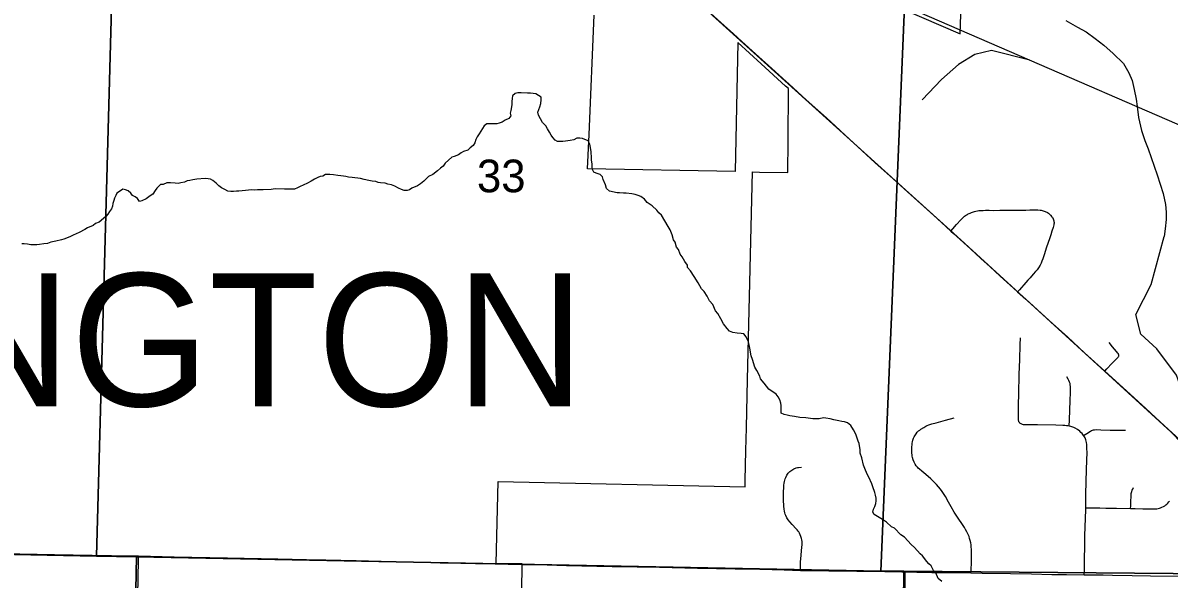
# Model space of a CAD drawing. Extents: x 0 to 34, y 0 to 22.
# Drawn here: x 25.012 to 25.746, y 18.367 to 18.723 of the extents above; entities that cross this region are included whole.
import ezdxf

# ---------------------------------------------------------------- set-up
doc = ezdxf.new("R2010")
doc.units = 0
for name, color, linetype in [('GM_X_City_Street', 7, 'Continuous'), ('GM_X_Corporation', 7, 'Continuous'), ('GM_X_County_Road', 7, 'Continuous'), ('GM_X_Major_River', 7, 'Continuous'), ('GM_X_Major_River_Text', 7, 'Continuous'), ('GM_X_Minor_River', 7, 'Continuous'), ('GM_X_Rail_Line', 7, 'Continuous'), ('GM_X_Section', 7, 'Continuous'), ('GM_X_Section_Text', 7, 'Continuous'), ('GM_X_State_Route', 7, 'Continuous'), ('GM_X_Township_Road', 7, 'Continuous'), ('GM_X_Township_Text', 7, 'Continuous'), ('GM_X_US_Route', 7, 'Continuous')]:
    doc.layers.add(name, color=color, linetype=linetype)

msp = doc.modelspace()

# ---------------------------------------------------------------- linework, layer by layer
at = {"layer": 'GM_X_City_Street'}
for points in [[(25.60654, 18.58985), (25.60774, 18.59127), (25.61008, 18.59407), (25.61296, 18.59711), (25.61376, 18.59796), (25.61444, 18.59863), (25.61534, 18.59937), (25.61649, 18.60019), (25.61713, 18.60055), (25.61771, 18.60086), (25.61892, 18.60142), (25.61964, 18.60174), (25.6204, 18.60204), (25.62097, 18.60223), (25.62159, 18.60241), (25.62258, 18.60264), (25.62356, 18.60284), (25.62434, 18.60297), (25.6257, 18.60309), (25.6273, 18.60317), (25.62866, 18.60319), (25.63106, 18.60318), (25.63353, 18.60316), (25.63795, 18.60319), (25.64313, 18.60328), (25.64983, 18.60334), (25.65463, 18.60338), (25.65722, 18.60342), (25.66006, 18.60344), (25.66228, 18.60342), (25.6638, 18.60329), (25.66448, 18.6032), (25.66508, 18.60309), (25.66577, 18.60292), (25.66639, 18.60272), (25.6669, 18.60252), (25.66746, 18.60229), (25.66801, 18.60201), (25.66853, 18.60172), (25.66906, 18.60135), (25.66955, 18.60098), (25.66998, 18.60057), (25.67043, 18.6001), (25.67124, 18.5991), (25.67153, 18.59868), (25.67177, 18.59828), (25.67208, 18.59766), (25.67235, 18.59701), (25.67251, 18.59642), (25.6726, 18.59591), (25.67264, 18.59536), (25.67266, 18.59488), (25.6726, 18.59437), (25.67247, 18.5938), (25.67227, 18.593), (25.672, 18.59213), (25.67128, 18.5899), (25.6705, 18.58747), (25.66964, 18.5848), (25.66887, 18.58248), (25.66766, 18.57897), (25.66651, 18.57535), (25.66545, 18.57206), (25.66491, 18.57058), (25.66433, 18.56922), (25.66368, 18.56803), (25.66265, 18.56635), (25.66175, 18.56507), (25.66084, 18.56392), (25.65928, 18.56215), (25.65735, 18.55998), (25.65591, 18.55849), (25.65447, 18.55697), (25.65044, 18.55229), (25.64924, 18.55089)], [(25.69204, 18.36949), (25.69207, 18.37266), (25.69215, 18.37961), (25.69228, 18.38766), (25.69236, 18.39038), (25.69248, 18.39453), (25.69294, 18.41109), (25.69296, 18.41238), (25.69311, 18.42103), (25.69354, 18.43688), (25.69378, 18.44836), (25.69376, 18.45006), (25.69366, 18.45168), (25.69359, 18.45297), (25.69342, 18.45416), (25.69327, 18.45503), (25.69302, 18.45592), (25.6928, 18.45664), (25.6925, 18.45731), (25.69211, 18.45799), (25.69162, 18.45872), (25.69061, 18.45996), (25.68981, 18.46078), (25.68909, 18.46144), (25.68765, 18.46255), (25.68611, 18.46349), (25.68542, 18.46383), (25.68475, 18.46412), (25.68332, 18.46458), (25.68227, 18.4648), (25.68155, 18.46493), (25.68061, 18.46506), (25.67946, 18.46518), (25.67818, 18.46525), (25.67386, 18.46538), (25.66207, 18.4656), (25.65491, 18.46557), (25.65391, 18.4656), (25.65342, 18.46564), (25.65297, 18.4657), (25.65249, 18.46581), (25.65196, 18.46599), (25.65151, 18.46622), (25.65109, 18.46647), (25.65079, 18.46673), (25.65055, 18.467), (25.65034, 18.46728), (25.65018, 18.46762), (25.65005, 18.46794), (25.64995, 18.46829), (25.64986, 18.46877), (25.64981, 18.46962), (25.64988, 18.47846), (25.65005, 18.48553), (25.65038, 18.49798), (25.65069, 18.50754), (25.65099, 18.51684), (25.65112, 18.52137)], [(25.70515, 18.50002), (25.70656, 18.50153), (25.70967, 18.50485), (25.71306, 18.50836), (25.71372, 18.50905), (25.71394, 18.50937), (25.71409, 18.50963), (25.71415, 18.50995), (25.71413, 18.51024), (25.71409, 18.51054), (25.714, 18.51079), (25.7139, 18.51106), (25.71376, 18.51128), (25.71361, 18.51152), (25.71266, 18.51264), (25.71018, 18.51552), (25.7079, 18.51838)], [(25.68227, 18.4648), (25.6826, 18.46884), (25.68305, 18.48125), (25.68317, 18.48627), (25.68317, 18.48889), (25.68313, 18.49025), (25.68304, 18.49118), (25.68289, 18.49214), (25.68264, 18.493), (25.68219, 18.49403), (25.68169, 18.49494), (25.68091, 18.49646)], [(25.61941, 18.37057), (25.61947, 18.37221), (25.61968, 18.37776), (25.61976, 18.38257), (25.61976, 18.38425), (25.61972, 18.38581), (25.61963, 18.38721), (25.61947, 18.38861), (25.61922, 18.38997), (25.61894, 18.39136), (25.61853, 18.39272), (25.61816, 18.39387), (25.61762, 18.39527), (25.6168, 18.39699), (25.61593, 18.39855), (25.61524, 18.39977), (25.6145, 18.401), (25.6131, 18.40303), (25.61207, 18.40452), (25.60874, 18.40957), (25.60677, 18.41294), (25.60504, 18.41606), (25.60303, 18.41956), (25.60093, 18.42289), (25.59987, 18.42432), (25.59867, 18.42576), (25.59727, 18.42729), (25.59608, 18.42852), (25.59371, 18.43091), (25.59041, 18.43374), (25.58782, 18.43583), (25.58643, 18.43711), (25.58564, 18.43781), (25.58507, 18.43849), (25.58437, 18.43929), (25.58367, 18.4404), (25.58305, 18.44159), (25.58243, 18.44309), (25.58197, 18.44457), (25.58178, 18.44553), (25.58166, 18.44641), (25.58158, 18.44742), (25.58151, 18.44858), (25.58155, 18.45138), (25.58162, 18.45268), (25.58176, 18.45386), (25.58195, 18.45478), (25.58213, 18.45569), (25.58236, 18.45642), (25.58264, 18.45715), (25.58297, 18.45786), (25.58333, 18.45855), (25.58419, 18.45984), (25.58497, 18.46079), (25.58586, 18.46166), (25.58659, 18.46226), (25.58732, 18.46281), (25.58915, 18.46397), (25.5905, 18.46474), (25.59132, 18.46512), (25.59242, 18.46555), (25.59436, 18.46616), (25.59711, 18.46695), (25.60299, 18.46851), (25.60874, 18.47019)], [(25.69162, 18.45872), (25.69366, 18.46009), (25.69592, 18.46161), (25.69658, 18.46198), (25.69736, 18.46227), (25.69794, 18.46239), (25.69855, 18.46247), (25.70003, 18.46251), (25.70262, 18.46247), (25.70854, 18.46227), (25.71364, 18.46218), (25.71853, 18.4621)], [(25.5102, 18.37225), (25.51021, 18.37343), (25.51023, 18.37778), (25.51033, 18.3796), (25.51103, 18.38724), (25.51111, 18.38864), (25.51115, 18.38979), (25.51111, 18.39081), (25.51099, 18.3918), (25.51074, 18.39275), (25.51045, 18.3939), (25.51004, 18.39513), (25.50955, 18.39608), (25.50902, 18.3969), (25.50861, 18.39739), (25.50795, 18.39821), (25.50729, 18.39891), (25.50482, 18.40163), (25.50326, 18.40335), (25.50223, 18.40467), (25.50137, 18.40602), (25.50067, 18.4075), (25.50034, 18.40828), (25.50006, 18.40919), (25.49981, 18.41026), (25.49965, 18.41145), (25.49944, 18.41344), (25.49924, 18.41749), (25.49919, 18.41971), (25.49926, 18.42238), (25.49944, 18.42571), (25.49952, 18.42694), (25.4997, 18.42826), (25.49989, 18.42925), (25.5001, 18.43008), (25.50038, 18.43093), (25.50071, 18.43185), (25.5014, 18.43324), (25.50182, 18.43389), (25.50229, 18.43451), (25.50337, 18.43563), (25.50458, 18.4366), (25.50515, 18.43697), (25.50592, 18.43739), (25.50737, 18.43795), (25.50824, 18.43816), (25.50888, 18.43828), (25.51074, 18.43846)], [(25.72174, 18.41188), (25.72178, 18.41363), (25.72187, 18.41675), (25.72203, 18.41942), (25.72215, 18.42152), (25.72224, 18.42217), (25.7224, 18.42287), (25.72269, 18.42361), (25.72306, 18.42431), (25.72367, 18.42534)], [(25.69296, 18.41238), (25.6953, 18.41235), (25.70196, 18.41227), (25.70578, 18.41219), (25.71264, 18.41207), (25.72174, 18.41188), (25.7247, 18.41183), (25.72966, 18.41174), (25.73496, 18.41165), (25.7364, 18.41165), (25.73763, 18.41174), (25.73858, 18.41182), (25.73936, 18.41194), (25.74014, 18.41211), (25.74096, 18.41239), (25.74178, 18.41272), (25.74273, 18.41322), (25.74363, 18.41375), (25.74429, 18.41425), (25.74495, 18.41478), (25.74561, 18.4154), (25.74626, 18.41614), (25.74671, 18.41667)]]:
    msp.add_lwpolyline(points, dxfattribs=at)
at = {"layer": 'GM_X_Corporation'}
for points in [[(25.57521, 18.73251), (25.61242, 18.71629), (25.61262, 18.7224), (25.6137, 18.7556)], [(25.33138, 18.3409), (25.33169, 18.37638), (25.3227, 18.37651), (25.3152, 18.37668), (25.31644, 18.42935), (25.47462, 18.42591), (25.47471, 18.4298), (25.47517, 18.44906), (25.47551, 18.46361), (25.47624, 18.49464), (25.47938, 18.6278), (25.48381, 18.62772), (25.50212, 18.62736), (25.50224, 18.64752), (25.50244, 18.68121), (25.50064, 18.68284), (25.485, 18.69705), (25.46995, 18.71072), (25.46827, 18.62802), (25.37372, 18.62988), (25.37465, 18.65172), (25.37789, 18.72832)]]:
    msp.add_lwpolyline(points, dxfattribs=at)
at = {"layer": 'GM_X_County_Road'}
msp.add_lwpolyline([(25.57356, 18.11072), (25.57386, 18.13412), (25.57414, 18.14773), (25.57415, 18.14935), (25.57414, 18.15015), (25.5745, 18.17231), (25.57479, 18.1866), (25.57499, 18.20213), (25.57512, 18.21331), (25.57564, 18.23224), (25.57583, 18.24747), (25.57605, 18.25958), (25.5761, 18.28008), (25.57622, 18.29313), (25.5763, 18.30679), (25.57637, 18.31765), (25.57648, 18.33593), (25.57685, 18.35206), (25.57691, 18.35431), (25.57724, 18.36728), (25.57732, 18.37128)], dxfattribs=at)
at = {"layer": 'GM_X_Major_River'}
for points in [[(25.68013, 18.72491), (25.68759, 18.72069), (25.69319, 18.71766), (25.69893, 18.71331), (25.70449, 18.70914), (25.71059, 18.70382), (25.71722, 18.69735), (25.72063, 18.69135), (25.72275, 18.68635), (25.7239, 18.68062), (25.72522, 18.6745), (25.72583, 18.66973), (25.72674, 18.66268), (25.72876, 18.65445), (25.73083, 18.64792), (25.73293, 18.64254), (25.73485, 18.63716), (25.73676, 18.6316), (25.73867, 18.62584), (25.74057, 18.61989), (25.74265, 18.61394), (25.74414, 18.60687), (25.74456, 18.6021), (25.74441, 18.59736)], [(25.74441, 18.59736), (25.74383, 18.5913), (25.7433, 18.58638)], [(25.80535, 18.45028), (25.78376, 18.45991), (25.75853, 18.47646), (25.75107, 18.49751), (25.73857, 18.51432), (25.72835, 18.52368), (25.72505, 18.53628), (25.73483, 18.55559), (25.7433, 18.58638)]]:
    msp.add_lwpolyline(points, dxfattribs=at)
at = {"layer": 'GM_X_Minor_River'}
for points in [[(25.42539, 18.59274), (25.42104, 18.60004), (25.41939, 18.60162), (25.41811, 18.60319), (25.41498, 18.60614), (25.41182, 18.60815), (25.41019, 18.6103), (25.40778, 18.61209), (25.40609, 18.61272), (25.40422, 18.61335), (25.40214, 18.6138), (25.39836, 18.61412), (25.39665, 18.61417), (25.3942, 18.61444), (25.39268, 18.6145), (25.38778, 18.61542), (25.38575, 18.6172), (25.38507, 18.6195), (25.38366, 18.62297), (25.38334, 18.6247), (25.38168, 18.62609), (25.37924, 18.62693), (25.37774, 18.62755), (25.37685, 18.62929), (25.37672, 18.63101), (25.3766, 18.6331), (25.37629, 18.6354), (25.37615, 18.63692), (25.3759, 18.64073), (25.37561, 18.64341), (25.37511, 18.64552), (25.37405, 18.64783), (25.37049, 18.64928), (25.36879, 18.64953), (25.36689, 18.6494), (25.36496, 18.64833), (25.36248, 18.64803), (25.35962, 18.64756), (25.35791, 18.64742), (25.35639, 18.64728), (25.35449, 18.64735), (25.35281, 18.64816), (25.35135, 18.64992), (25.35026, 18.65148), (25.34918, 18.65323), (25.34793, 18.65536), (25.34685, 18.6573), (25.34483, 18.65946), (25.34233, 18.66411), (25.34183, 18.66603), (25.34246, 18.66791), (25.34308, 18.6696), (25.34372, 18.67167), (25.34399, 18.67414), (25.34404, 18.67566), (25.34051, 18.67787), (25.33711, 18.67836), (25.33521, 18.67842), (25.33104, 18.67856), (25.32895, 18.67844), (25.32724, 18.67812), (25.32567, 18.67665), (25.32542, 18.67495), (25.32517, 18.67305), (25.32511, 18.67115), (25.32486, 18.66945), (25.32441, 18.66718), (25.32416, 18.66548), (25.32449, 18.66375), (25.32329, 18.66208), (25.32079, 18.66102), (25.31904, 18.65975), (25.31712, 18.65905), (25.3156, 18.65872), (25.31388, 18.65859), (25.30915, 18.65875), (25.30739, 18.65729), (25.30639, 18.65561), (25.30519, 18.65394), (25.30419, 18.65226), (25.30299, 18.6504), (25.30217, 18.64852), (25.30134, 18.64646), (25.30034, 18.64478), (25.29839, 18.64332), (25.29702, 18.64185), (25.29414, 18.64099), (25.2926, 18.64009), (25.29104, 18.63881), (25.28816, 18.63777), (25.28662, 18.63725), (25.28251, 18.63339), (25.28112, 18.63153), (25.27937, 18.63026), (25.27742, 18.62861), (25.27449, 18.62605), (25.27179, 18.62481), (25.27023, 18.62334), (25.26866, 18.62187), (25.26652, 18.62023), (25.26458, 18.61896)], [(25.26458, 18.61896), (25.26112, 18.61737), (25.25956, 18.61628), (25.25803, 18.61595), (25.25613, 18.61582), (25.25445, 18.61645), (25.25258, 18.61746), (25.25016, 18.61868), (25.2481, 18.61951), (25.24565, 18.61997), (25.24396, 18.6206), (25.24093, 18.62089), (25.23942, 18.62113), (25.23792, 18.62156), (25.23565, 18.62183), (25.23358, 18.62228), (25.23057, 18.62295), (25.22812, 18.6236), (25.22283, 18.62416), (25.22056, 18.62443), (25.21868, 18.62487), (25.21717, 18.62511), (25.21547, 18.62536), (25.21358, 18.62561), (25.21074, 18.6259), (25.20848, 18.62616), (25.20563, 18.62607), (25.20408, 18.62517), (25.20236, 18.62484), (25.20082, 18.62413), (25.1987, 18.62306), (25.19657, 18.6218), (25.19425, 18.62055), (25.19137, 18.61931), (25.18944, 18.61843), (25.1877, 18.61754), (25.18578, 18.61684), (25.18274, 18.61675), (25.18104, 18.61681), (25.17952, 18.61667), (25.17345, 18.61687), (25.17098, 18.61657), (25.16585, 18.61636), (25.16414, 18.61623), (25.16205, 18.6163), (25.16015, 18.61617), (25.15825, 18.61624), (25.15445, 18.61598), (25.15026, 18.61555), (25.14874, 18.61541), (25.14665, 18.61529), (25.14494, 18.61516), (25.14305, 18.61541), (25.14119, 18.61662), (25.13914, 18.61764), (25.13728, 18.61884), (25.13563, 18.62061), (25.13341, 18.62239), (25.13192, 18.6232), (25.13041, 18.62344), (25.12852, 18.62351), (25.12319, 18.62311), (25.12071, 18.62263), (25.1188, 18.62231), (25.11709, 18.62199), (25.11536, 18.62128), (25.11306, 18.62079), (25.11135, 18.62047), (25.10926, 18.62054), (25.10642, 18.62082), (25.10395, 18.62071), (25.10165, 18.61984), (25.09994, 18.61971), (25.09758, 18.61731), (25.09658, 18.61583), (25.09499, 18.6136), (25.09344, 18.61251), (25.09072, 18.61051), (25.08802, 18.60926), (25.08649, 18.60894), (25.08522, 18.61069), (25.08374, 18.61188), (25.08206, 18.6127), (25.08097, 18.61426), (25.07931, 18.61564), (25.07744, 18.61628), (25.07574, 18.61671), (25.07361, 18.61526), (25.07206, 18.61417), (25.07144, 18.61267), (25.07043, 18.61099), (25.07001, 18.60949), (25.06937, 18.60761), (25.06913, 18.6059), (25.0685, 18.60421), (25.0673, 18.60235), (25.06611, 18.60068), (25.06492, 18.5992)], [(25.06492, 18.5992), (25.06063, 18.59558), (25.05832, 18.59471), (25.05676, 18.59344), (25.05309, 18.59185), (25.05153, 18.59096), (25.04785, 18.589), (25.04399, 18.58723), (25.04224, 18.58634), (25.04071, 18.58583), (25.03801, 18.58478), (25.03647, 18.58427), (25.03283, 18.58344), (25.02976, 18.58279), (25.02745, 18.58192), (25.02516, 18.58162), (25.02248, 18.58134), (25.02076, 18.58102), (25.01696, 18.58115), (25.01469, 18.58142), (25.01261, 18.58168), (25.01109, 18.58173)], [(25.48688, 18.49239), (25.4845, 18.49513), (25.48418, 18.49686), (25.48222, 18.50034), (25.48096, 18.50248), (25.47942, 18.50747), (25.47856, 18.50978), (25.47778, 18.51474), (25.47678, 18.51877), (25.47537, 18.52205), (25.47392, 18.524), (25.47203, 18.52425), (25.46956, 18.52434), (25.46673, 18.52482), (25.46466, 18.52565), (25.4632, 18.52741), (25.46084, 18.53034), (25.45905, 18.53363), (25.45708, 18.53693), (25.45562, 18.53869), (25.45386, 18.54274), (25.45185, 18.54509), (25.45025, 18.54819), (25.44845, 18.5511), (25.44661, 18.55287), (25.44465, 18.55674), (25.44194, 18.56063), (25.4396, 18.56432), (25.43777, 18.56648), (25.43764, 18.568), (25.43601, 18.57034), (25.43441, 18.57343), (25.43313, 18.575), (25.43191, 18.57808), (25.43063, 18.57964), (25.42979, 18.58271), (25.4287, 18.58427), (25.42787, 18.58753), (25.42664, 18.59061), (25.42539, 18.59274)], [(25.60066, 18.36515), (25.59845, 18.36713), (25.59686, 18.3706), (25.59539, 18.37217), (25.59397, 18.37507), (25.59231, 18.37646), (25.59122, 18.37802), (25.58831, 18.38154), (25.58683, 18.38292), (25.58317, 18.38685), (25.58115, 18.38881), (25.57675, 18.39353), (25.57453, 18.39512), (25.57049, 18.39925), (25.56843, 18.40027), (25.5653, 18.40323), (25.5627, 18.40484), (25.55954, 18.40685), (25.5573, 18.40807), (25.55659, 18.40961), (25.55685, 18.41151), (25.55786, 18.41318), (25.5585, 18.41506), (25.55875, 18.41676), (25.55862, 18.41847), (25.55812, 18.42058), (25.5578, 18.4223), (25.55659, 18.42576), (25.5559, 18.42769), (25.55396, 18.43212), (25.55288, 18.43387), (25.5513, 18.43753), (25.55062, 18.43965), (25.54945, 18.44444), (25.54842, 18.44751), (25.5483, 18.4496), (25.54769, 18.45361), (25.54717, 18.45515), (25.54648, 18.45708), (25.54561, 18.45958), (25.54419, 18.46247), (25.54239, 18.4652), (25.54036, 18.46698), (25.53829, 18.46762), (25.53658, 18.46768), (25.5347, 18.46812), (25.53149, 18.46881), (25.52923, 18.46945), (25.5264, 18.46993), (25.52488, 18.46999), (25.5222, 18.46951), (25.52048, 18.46938), (25.51801, 18.46946), (25.51366, 18.47), (25.50968, 18.47032), (25.50628, 18.47101), (25.50325, 18.47131), (25.50155, 18.47175), (25.49967, 18.47219), (25.49779, 18.47302), (25.49786, 18.47491), (25.49778, 18.47796), (25.49764, 18.47948), (25.49696, 18.4816), (25.49588, 18.48353), (25.49461, 18.48529), (25.48978, 18.48849), (25.48688, 18.49239)]]:
    msp.add_lwpolyline(points, dxfattribs=at)
at = {"layer": 'GM_X_Rail_Line'}
for points in [[(25.87823, 18.60359), (25.53019, 18.75466), (25.45032, 18.78944), (25.32842, 18.84239), (25.27725, 18.86493), (25.16636, 18.91338), (25.04289, 18.96722), (24.97136, 18.99851)], [(26.12662, 18.3677), (25.96016, 18.37069), (25.83521, 18.37068), (25.74745, 18.46115), (25.61049, 18.58632), (25.32774, 18.84221)], [(25.65707, 18.69959), (25.63265, 18.70568), (25.6218, 18.70321), (25.61144, 18.6968), (25.60059, 18.68718), (25.58802, 18.67411)]]:
    msp.add_lwpolyline(points, dxfattribs=at)
at = {"layer": 'GM_X_Section'}
for points in [[(24.56605, 18.89955), (25.0729, 18.88974), (25.05902, 18.38136), (24.5641, 18.39149), (24.55748, 18.39165)], [(25.0729, 18.88974), (25.58303, 18.88231), (25.5617, 18.37181), (25.08458, 18.38093), (25.05902, 18.38136)], [(25.58303, 18.88231), (26.08209, 18.87154), (26.06944, 18.36744), (25.57628, 18.37165), (25.5617, 18.37181)], [(24.5641, 18.39149), (25.05902, 18.38136), (25.08458, 18.38093), (25.07407, 17.86217), (24.61766, 17.87438)], [(25.08458, 18.38093), (25.5617, 18.37181), (25.57628, 18.37165), (25.57077, 17.84822), (25.07407, 17.86217)], [(25.57628, 18.37165), (26.06944, 18.36744), (26.0861, 18.36703), (26.07549, 17.83653), (25.57077, 17.84822)]]:
    msp.add_lwpolyline(points, close=True, dxfattribs=at)
at = {"layer": 'GM_X_State_Route'}
for p, q in [((25.31437, 18.37644), (25.31537, 18.37641)), ((25.32933, 18.37615), (25.33183, 18.37611))]:
    msp.add_line(p, q, dxfattribs=at)
for points in [[(24.73353, 18.38834), (24.74003, 18.38824), (24.76861, 18.38767), (24.78382, 18.38734), (24.80028, 18.38706), (24.81612, 18.38662), (24.82886, 18.38637), (24.83817, 18.38619), (24.85277, 18.38594), (24.86674, 18.38569), (24.87948, 18.38543), (24.89873, 18.38502), (24.92202, 18.38447), (24.94439, 18.38409), (24.96085, 18.38379), (24.97638, 18.38346), (25.03198, 18.38251), (25.0562, 18.38196), (25.08105, 18.38157), (25.08595, 18.38147)], [(25.08595, 18.38147), (25.10869, 18.38104), (25.14285, 18.3803), (25.17515, 18.37959), (25.19347, 18.37915), (25.2059, 18.37891), (25.22546, 18.37848), (25.25744, 18.37776), (25.26924, 18.37745), (25.27918, 18.37719), (25.29254, 18.37697), (25.30186, 18.37675), (25.31437, 18.37644)], [(25.31537, 18.37641), (25.32282, 18.37624), (25.32933, 18.37615)], [(25.33183, 18.37611), (25.33874, 18.37594), (25.34775, 18.37576), (25.36018, 18.37542), (25.38937, 18.37478), (25.40553, 18.37456), (25.41981, 18.37426), (25.44404, 18.37377), (25.46827, 18.37321), (25.48411, 18.37292), (25.49964, 18.37253), (25.5102, 18.37225), (25.51268, 18.37218), (25.52821, 18.37194), (25.56421, 18.37143), (25.57508, 18.37133), (25.57732, 18.37128), (25.5847, 18.37113), (25.59434, 18.37087), (25.60273, 18.37081), (25.61941, 18.37057), (25.62664, 18.37047), (25.64465, 18.37021), (25.65829, 18.37), (25.67129, 18.36969), (25.6806, 18.36963), (25.69204, 18.36949), (25.69737, 18.36942), (25.70418, 18.36936), (25.71006, 18.36925)], [(25.71006, 18.36925), (25.72279, 18.36904), (25.73457, 18.36883), (25.75751, 18.36846), (25.7693, 18.36824), (25.77891, 18.36805), (25.80412, 18.36764), (25.80848, 18.36764), (25.81378, 18.36792), (25.81967, 18.36845), (25.82089, 18.36862), (25.82892, 18.36974), (25.83379, 18.37066), (25.83712, 18.3713)]]:
    msp.add_lwpolyline(points, dxfattribs=at)
at = {"layer": 'GM_X_Township_Road'}
msp.add_lwpolyline([(25.07438, 17.83062), (25.07573, 17.90392), (25.076, 17.91977), (25.0765, 17.94616), (25.07784, 17.99958), (25.07844, 18.03187), (25.07919, 18.0546), (25.07956, 18.06883), (25.07978, 18.08459), (25.08029, 18.11146), (25.08172, 18.17161), (25.08246, 18.19925), (25.08293, 18.22596), (25.08322, 18.24304), (25.08366, 18.26168), (25.08401, 18.27752), (25.08453, 18.31112), (25.08589, 18.37878), (25.08595, 18.38147)], dxfattribs=at)
at = {"layer": 'GM_X_US_Route'}
msp.add_line((25.47004, 18.71385), (25.4726, 18.71154), dxfattribs=at)
for points in [[(25.40516, 18.77263), (25.42138, 18.75786), (25.43371, 18.74673), (25.46129, 18.72174), (25.46708, 18.7166), (25.47004, 18.71385)], [(25.4726, 18.71154), (25.48137, 18.70362), (25.49387, 18.69228), (25.50089, 18.68587), (25.50262, 18.68423)], [(25.50262, 18.68423), (25.51376, 18.67409), (25.52674, 18.6624), (25.53266, 18.65705), (25.53882, 18.65146), (25.55788, 18.63394), (25.56952, 18.62347), (25.57654, 18.61706), (25.59773, 18.59787), (25.60654, 18.58985), (25.6082, 18.58833), (25.61908, 18.5784), (25.62572, 18.57231), (25.63167, 18.56685), (25.63812, 18.56101), (25.64451, 18.55511), (25.64924, 18.55089), (25.65448, 18.54622), (25.67187, 18.53038), (25.6812, 18.52199), (25.69212, 18.51187), (25.70515, 18.50002), (25.71901, 18.48743), (25.73138, 18.476), (25.74059, 18.46762), (25.7532, 18.45595)]]:
    msp.add_lwpolyline(points, dxfattribs=at)

# ---------------------------------------------------------------- texts
at = {"layer": 'GM_X_Major_River_Text'}
msp.add_text('Creek', height=0.047335, rotation=316.62793, dxfattribs=at).set_placement((25.69861, 18.81588))
at = {"layer": 'GM_X_Section_Text'}
msp.add_text('33', height=0.020928, rotation=0.00001, dxfattribs=at).set_placement((25.30279, 18.61477))
at = {"layer": 'GM_X_Township_Text'}
msp.add_text('WASHINGTON', height=0.085227, rotation=0.00001, dxfattribs=at).set_placement((24.58661, 18.4775))

doc.saveas('drawing.dxf')
